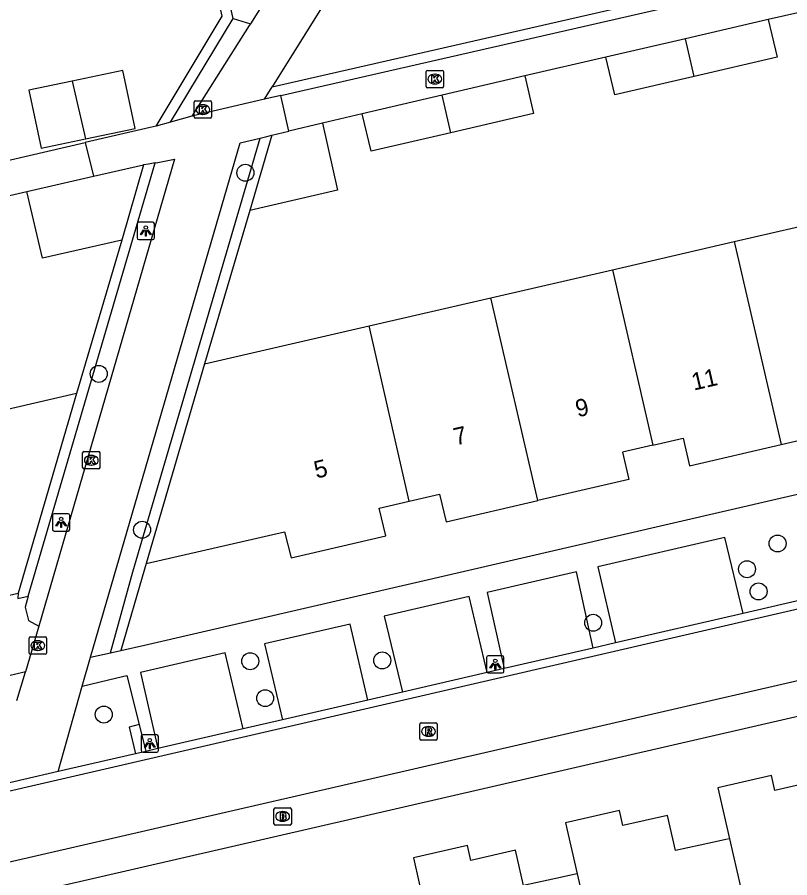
# Model space of a CAD drawing. Extents: x 156414 to 157775, y 382335 to 383765.
# Drawn here: x 156721.03 to 156765.54, y 382800.66 to 382850.26 of the extents above; entities that cross this region are included whole.
import ezdxf

# ---------------------------------------------------------------- set-up
doc = ezdxf.new("R2010")
doc.units = 0
for name, color, linetype in [('IMGEO_Berm_groen', 7, 'Continuous'), ('IMGEO_Boom', 7, 'Continuous'), ('IMGEO_Brandkraan', 7, 'Continuous'), ('IMGEO_Groenvoorziening', 7, 'Continuous'), ('IMGEO_Haag', 7, 'Continuous'), ('IMGEO_Kolk', 7, 'Continuous'), ('IMGEO_Lichtpunt', 7, 'Continuous'), ('IMGEO_Pand', 7, 'Continuous'), ('IMGEO_Pand_nummerreeks', 7, 'Continuous'), ('IMGEO_Rijbaan_lokaal_gesloten', 7, 'Continuous'), ('IMGEO_Rijbaan_lokaal_open', 7, 'Continuous'), ('IMGEO_Rioolput', 7, 'Continuous'), ('IMGEO_Voetpad_open', 7, 'Continuous')]:
    doc.layers.add(name, color=color, linetype=linetype)

msp = doc.modelspace()

# ---------------------------------------------------------------- linework, layer by layer
at = {"layer": 'IMGEO_Berm_groen'}
msp.add_lwpolyline([(156721.664, 382816.893), (156721.493, 382816.251), (156721.685, 382815.494), (156722.274, 382815.156)], dxfattribs=at)
at = {"layer": 'IMGEO_Boom'}
for centre in [(156734.173, 382841.29), (156725.727, 382829.702), (156728.226, 382820.715), (156764.843, 382819.925), (156763.079, 382818.443), (156763.742, 382817.164), (156754.215, 382815.36), (156734.456, 382813.141), (156742.063, 382813.189), (156735.315, 382811.011), (156726.015, 382810.066)]:
    msp.add_circle(centre, 0.489, dxfattribs=at)
at = {"layer": 'IMGEO_Brandkraan'}
for p, q in [((156735.897, 382804.694), (156736.749, 382804.694)), ((156735.822, 382803.768), (156735.822, 382804.62)), ((156736.31, 382804.474), (156736.335, 382804.474)), ((156736.823, 382804.62), (156736.823, 382803.768)), ((156736.749, 382803.694), (156735.897, 382803.694)), ((156736.333, 382803.914), (156736.308, 382803.914))]:
    msp.add_line(p, q, dxfattribs=at)
for points in [[(156735.897, 382804.694), (156736.749, 382804.694)], [(156735.822, 382803.768), (156735.822, 382804.62)], [(156736.17, 382804.394), (156736.17, 382803.994), (156736.383, 382803.994)], [(156736.401, 382804.394), (156736.17, 382804.394)], [(156736.349, 382804.313), (156736.295, 382804.313), (156736.295, 382804.237)], [(156736.295, 382804.237), (156736.348, 382804.237)], [(156736.823, 382804.62), (156736.823, 382803.768)], [(156736.749, 382803.694), (156735.897, 382803.694)], [(156736.357, 382804.161), (156736.295, 382804.161), (156736.295, 382804.08)], [(156736.295, 382804.08), (156736.357, 382804.08)]]:
    msp.add_lwpolyline(points, dxfattribs=at)
for centre, radius, start, end in [((156735.899, 382804.618), 0.0765, 91.552, 178.448), ((156735.899, 382804.618), 0.0765, 91.552, 178.448), ((156736.747, 382804.618), 0.0765, 1.552, 88.448), ((156736.747, 382804.618), 0.0765, 1.552, 88.448), ((156736.35, 382804.275), 0.0379, 267.8285, 90.9355), ((156736.405, 382804.249), 0.145, 59.4692, 91.5367), ((156736.43, 382804.296), 0.0922, 285.5137, 58.1501), ((156736.435, 382804.104), 0.105, 301.3115, 78.989), ((156735.899, 382803.77), 0.0765, 181.552, 268.448), ((156735.899, 382803.77), 0.0765, 181.552, 268.448), ((156736.358, 382804.12), 0.0404, 269.8759, 90.5077), ((156736.389, 382804.245), 0.251, 268.6676, 293.5347), ((156736.747, 382803.77), 0.0765, 271.552, 358.448), ((156736.747, 382803.77), 0.0765, 271.552, 358.448)]:
    msp.add_arc(centre, radius, start, end, dxfattribs=at)
for centre, major_axis, ratio, start_param, end_param in [((156736.309, 382804.194), (-0.387, 0.002), 0.722429, 4.712389, 7.853982), ((156736.334, 382804.194), (-0.39, 0.002), 0.717154, 1.570796, 4.712389)]:
    msp.add_ellipse(centre, major_axis=major_axis, ratio=ratio, start_param=start_param, end_param=end_param, dxfattribs=at)
at = {"layer": 'IMGEO_Groenvoorziening'}
msp.add_lwpolyline([(156733.462, 382850.192), (156734.46, 382849.883)], dxfattribs=at)
at = {"layer": 'IMGEO_Haag'}
for points in [[(156733.462, 382850.192), (156729.614, 382867.185), (156746.459, 382871.069), (156750.554, 382877.778)], [(156729.028, 382843.982), (156732.84, 382850.322), (156731.46, 382856.456)], [(156735.72, 382846.251), (156762.237, 382852.326)], [(156729.869, 382844.215), (156733.462, 382850.192)], [(156726.403, 382813.631), (156727.692, 382818.286), (156735.021, 382843.289)], [(156721.664, 382816.893), (156728.973, 382841.864)], [(156734.427, 382839.126), (156731.822, 382830.272)], [(156727.052, 382837.412), (156724.448, 382828.561)], [(156728.459, 382818.77), (156728.362, 382818.44), (156726.991, 382813.763)], [(156721.09, 382817.069), (156721.055, 382816.753), (156721.664, 382816.893)], [(156728.053, 382809.486), (156727.47, 382809.343), (156727.852, 382807.81)]]:
    msp.add_lwpolyline(points, dxfattribs=at)
at = {"layer": 'IMGEO_Kolk'}
for p, q in [((156744.589, 382846.268), (156744.589, 382847.12)), ((156744.664, 382847.194), (156745.516, 382847.194)), ((156745.077, 382846.974), (156745.102, 382846.974)), ((156745.59, 382847.12), (156745.59, 382846.268)), ((156745.1, 382846.414), (156745.075, 382846.414)), ((156745.516, 382846.194), (156744.664, 382846.194)), ((156731.218, 382844.509), (156731.218, 382845.361)), ((156731.293, 382845.435), (156732.145, 382845.435)), ((156732.219, 382845.361), (156732.219, 382844.509)), ((156731.706, 382845.215), (156731.731, 382845.215)), ((156732.145, 382844.435), (156731.293, 382844.435)), ((156731.729, 382844.655), (156731.704, 382844.655)), ((156724.796, 382824.299), (156724.796, 382825.151)), ((156724.871, 382825.225), (156725.723, 382825.225)), ((156725.284, 382825.005), (156725.309, 382825.005)), ((156725.797, 382825.151), (156725.797, 382824.299)), ((156725.723, 382824.225), (156724.871, 382824.225)), ((156725.307, 382824.445), (156725.282, 382824.445)), ((156721.709, 382813.613), (156721.709, 382814.465)), ((156721.784, 382814.539), (156722.636, 382814.539)), ((156722.197, 382814.319), (156722.222, 382814.319)), ((156722.71, 382814.465), (156722.71, 382813.613)), ((156722.22, 382813.759), (156722.195, 382813.759)), ((156722.636, 382813.539), (156721.784, 382813.539))]:
    msp.add_line(p, q, dxfattribs=at)
for points in [[(156744.589, 382846.268), (156744.589, 382847.12)], [(156744.664, 382847.194), (156745.516, 382847.194)], [(156744.91, 382846.894), (156745.033, 382846.894), (156745.033, 382846.743), (156745.163, 382846.894), (156745.327, 382846.894), (156745.181, 382846.743), (156745.334, 382846.494), (156745.182, 382846.494), (156745.097, 382846.658), (156745.033, 382846.591), (156745.033, 382846.494), (156744.91, 382846.494), (156744.91, 382846.894)], [(156745.59, 382847.12), (156745.59, 382846.268)], [(156745.516, 382846.194), (156744.664, 382846.194)], [(156731.218, 382844.509), (156731.218, 382845.361)], [(156731.293, 382845.435), (156732.145, 382845.435)], [(156732.219, 382845.361), (156732.219, 382844.509)], [(156731.539, 382845.135), (156731.662, 382845.135), (156731.662, 382844.984), (156731.792, 382845.135), (156731.956, 382845.135), (156731.81, 382844.984), (156731.963, 382844.735), (156731.811, 382844.735), (156731.726, 382844.899), (156731.662, 382844.832), (156731.662, 382844.735), (156731.539, 382844.735), (156731.539, 382845.135)], [(156732.145, 382844.435), (156731.293, 382844.435)], [(156724.796, 382824.299), (156724.796, 382825.151)], [(156724.871, 382825.225), (156725.723, 382825.225)], [(156725.797, 382825.151), (156725.797, 382824.299)], [(156725.117, 382824.925), (156725.24, 382824.925), (156725.24, 382824.774), (156725.37, 382824.925), (156725.534, 382824.925), (156725.388, 382824.774), (156725.541, 382824.525), (156725.389, 382824.525), (156725.304, 382824.689), (156725.24, 382824.622), (156725.24, 382824.525), (156725.117, 382824.525), (156725.117, 382824.925)], [(156725.723, 382824.225), (156724.871, 382824.225)], [(156721.709, 382813.613), (156721.709, 382814.465)], [(156721.784, 382814.539), (156722.636, 382814.539)], [(156722.03, 382814.239), (156722.153, 382814.239), (156722.153, 382814.088), (156722.283, 382814.239), (156722.447, 382814.239), (156722.301, 382814.088), (156722.454, 382813.839), (156722.302, 382813.839), (156722.217, 382814.003), (156722.153, 382813.936), (156722.153, 382813.839), (156722.03, 382813.839), (156722.03, 382814.239)], [(156722.71, 382814.465), (156722.71, 382813.613)], [(156722.636, 382813.539), (156721.784, 382813.539)]]:
    msp.add_lwpolyline(points, dxfattribs=at)
for centre, start, end in [((156744.666, 382847.118), 91.552, 178.448), ((156744.666, 382847.118), 91.552, 178.448), ((156745.514, 382847.118), 1.552, 88.448), ((156745.514, 382847.118), 1.552, 88.448), ((156744.666, 382846.27), 181.552, 268.448), ((156744.666, 382846.27), 181.552, 268.448), ((156745.514, 382846.27), 271.552, 358.448), ((156745.514, 382846.27), 271.552, 358.448), ((156731.295, 382845.359), 91.552, 178.448), ((156731.295, 382845.359), 91.552, 178.448), ((156732.143, 382845.359), 1.552, 88.448), ((156732.143, 382845.359), 1.552, 88.448), ((156731.295, 382844.511), 181.552, 268.448), ((156731.295, 382844.511), 181.552, 268.448), ((156732.143, 382844.511), 271.552, 358.448), ((156732.143, 382844.511), 271.552, 358.448), ((156724.873, 382825.149), 91.552, 178.448), ((156724.873, 382825.149), 91.552, 178.448), ((156725.721, 382825.149), 1.552, 88.448), ((156725.721, 382825.149), 1.552, 88.448), ((156724.873, 382824.301), 181.552, 268.448), ((156724.873, 382824.301), 181.552, 268.448), ((156725.721, 382824.301), 271.552, 358.448), ((156725.721, 382824.301), 271.552, 358.448), ((156721.786, 382814.463), 91.552, 178.448), ((156721.786, 382814.463), 91.552, 178.448), ((156722.634, 382814.463), 1.552, 88.448), ((156722.634, 382814.463), 1.552, 88.448), ((156721.786, 382813.615), 181.552, 268.448), ((156721.786, 382813.615), 181.552, 268.448), ((156722.634, 382813.615), 271.552, 358.448), ((156722.634, 382813.615), 271.552, 358.448)]:
    msp.add_arc(centre, 0.0765, start, end, dxfattribs=at)
for centre, major_axis, ratio, start_param, end_param in [((156745.076, 382846.694), (-0.387, 0.002), 0.722429, 4.712389, 7.853982), ((156745.101, 382846.694), (-0.39, 0.002), 0.717154, 1.570796, 4.712389), ((156731.705, 382844.935), (-0.387, 0.002), 0.722429, 4.712389, 7.853982), ((156731.73, 382844.935), (-0.39, 0.002), 0.717154, 1.570796, 4.712389), ((156725.283, 382824.725), (-0.387, 0.002), 0.722429, 4.712389, 7.853982), ((156725.308, 382824.725), (-0.39, 0.002), 0.717154, 1.570796, 4.712389), ((156722.196, 382814.039), (-0.387, 0.002), 0.722429, 4.712389, 7.853982), ((156722.221, 382814.039), (-0.39, 0.002), 0.717154, 1.570796, 4.712389)]:
    msp.add_ellipse(centre, major_axis=major_axis, ratio=ratio, start_param=start_param, end_param=end_param, dxfattribs=at)
at = {"layer": 'IMGEO_Lichtpunt'}
for p, q in [((156728.84, 382838.437), (156728.032, 382838.437)), ((156728.84, 382838.437), (156728.032, 382838.437)), ((156727.938, 382838.342), (156727.938, 382837.535)), ((156727.938, 382838.342), (156727.938, 382837.535)), ((156728.934, 382837.535), (156728.934, 382838.342)), ((156728.934, 382837.535), (156728.934, 382838.342)), ((156728.032, 382837.441), (156728.84, 382837.441)), ((156728.032, 382837.441), (156728.84, 382837.441)), ((156723.059, 382821.545), (156723.059, 382820.738)), ((156723.059, 382821.545), (156723.059, 382820.738)), ((156723.961, 382821.64), (156723.153, 382821.64)), ((156723.961, 382821.64), (156723.153, 382821.64)), ((156724.055, 382820.738), (156724.055, 382821.545)), ((156724.055, 382820.738), (156724.055, 382821.545)), ((156723.153, 382820.644), (156723.961, 382820.644)), ((156723.153, 382820.644), (156723.961, 382820.644)), ((156748.077, 382813.363), (156748.077, 382812.556)), ((156748.077, 382813.363), (156748.077, 382812.556)), ((156748.979, 382813.458), (156748.171, 382813.458)), ((156748.979, 382813.458), (156748.171, 382813.458)), ((156749.073, 382812.556), (156749.073, 382813.363)), ((156749.073, 382812.556), (156749.073, 382813.363)), ((156748.171, 382812.462), (156748.979, 382812.462)), ((156748.171, 382812.462), (156748.979, 382812.462)), ((156728.166, 382808.793), (156728.166, 382807.986)), ((156728.166, 382808.793), (156728.166, 382807.986)), ((156729.068, 382808.888), (156728.26, 382808.888)), ((156729.068, 382808.888), (156728.26, 382808.888)), ((156729.162, 382807.986), (156729.162, 382808.793)), ((156729.162, 382807.986), (156729.162, 382808.793)), ((156728.26, 382807.892), (156729.068, 382807.892)), ((156728.26, 382807.892), (156729.068, 382807.892))]:
    msp.add_line(p, q, dxfattribs=at)
for points in [[(156728.312, 382838.006), (156728.351, 382837.978), (156728.163, 382837.716), (156728.125, 382837.743), (156728.312, 382838.006)], [(156728.414, 382837.958), (156728.461, 382837.958), (156728.461, 382837.636), (156728.414, 382837.636), (156728.414, 382837.958)], [(156728.524, 382837.978), (156728.562, 382838.005), (156728.749, 382837.743), (156728.71, 382837.715), (156728.524, 382837.978)], [(156723.433, 382821.209), (156723.472, 382821.181), (156723.284, 382820.919), (156723.246, 382820.946), (156723.433, 382821.209)], [(156723.535, 382821.161), (156723.582, 382821.161), (156723.582, 382820.839), (156723.535, 382820.839), (156723.535, 382821.161)], [(156723.645, 382821.181), (156723.683, 382821.208), (156723.87, 382820.946), (156723.831, 382820.918), (156723.645, 382821.181)], [(156748.451, 382813.027), (156748.49, 382812.999), (156748.302, 382812.737), (156748.264, 382812.764), (156748.451, 382813.027)], [(156748.553, 382812.979), (156748.6, 382812.979), (156748.6, 382812.657), (156748.553, 382812.657), (156748.553, 382812.979)], [(156748.663, 382812.999), (156748.701, 382813.026), (156748.888, 382812.764), (156748.849, 382812.736), (156748.663, 382812.999)], [(156728.54, 382808.457), (156728.579, 382808.429), (156728.391, 382808.167), (156728.353, 382808.194), (156728.54, 382808.457)], [(156728.642, 382808.409), (156728.689, 382808.409), (156728.689, 382808.087), (156728.642, 382808.087), (156728.642, 382808.409)], [(156728.752, 382808.429), (156728.79, 382808.456), (156728.977, 382808.194), (156728.938, 382808.166), (156728.752, 382808.429)]]:
    msp.add_lwpolyline(points, dxfattribs=at)
for centre in [(156728.437, 382838.14), (156723.558, 382821.343), (156748.576, 382813.161), (156728.665, 382808.591)]:
    msp.add_circle(centre, 0.0994, dxfattribs=at)
for centre, start, end in [((156728.032, 382838.342), 90, 180), ((156728.032, 382838.342), 90, 180), ((156728.84, 382838.342), 0, 90), ((156728.84, 382838.342), 0, 90), ((156728.032, 382837.535), 180, 270), ((156728.032, 382837.535), 180, 270), ((156728.84, 382837.535), 270, 0), ((156728.84, 382837.535), 270, 360), ((156723.153, 382821.545), 90, 180), ((156723.153, 382821.545), 90, 180), ((156723.961, 382821.545), 0, 90), ((156723.961, 382821.545), 0, 90), ((156723.153, 382820.738), 180, 270), ((156723.153, 382820.738), 180, 270), ((156723.961, 382820.738), 270, 0), ((156723.961, 382820.738), 270, 360), ((156748.171, 382813.363), 90, 180), ((156748.171, 382813.363), 90, 180), ((156748.979, 382813.363), 0, 90), ((156748.979, 382813.363), 0, 90), ((156748.171, 382812.556), 180, 270), ((156748.171, 382812.556), 180, 270), ((156748.979, 382812.556), 270, 0), ((156748.979, 382812.556), 270, 360), ((156728.26, 382808.793), 90, 180), ((156728.26, 382808.793), 90, 180), ((156729.068, 382808.793), 0, 90), ((156729.068, 382808.793), 0, 90), ((156728.26, 382807.986), 180, 270), ((156728.26, 382807.986), 180, 270), ((156729.068, 382807.986), 270, 0), ((156729.068, 382807.986), 270, 360)]:
    msp.add_arc(centre, 0.0946, start, end, dxfattribs=at)
at = {"layer": 'IMGEO_Pand'}
for points in [[(156764.29, 382850.124), (156759.529, 382849.02)], [(156764.29, 382850.124), (156764.82, 382847.954), (156760.03, 382846.849)], [(156759.529, 382849.02), (156754.942, 382847.957)], [(156760.03, 382846.849), (156759.529, 382849.02)], [(156760.03, 382846.849), (156755.457, 382845.794), (156754.942, 382847.957)], [(156724.967, 382843.252), (156727.822, 382843.851), (156727.121, 382847.192), (156724.198, 382846.579)], [(156750.279, 382846.872), (156745.506, 382845.761)], [(156750.279, 382846.872), (156750.781, 382844.707), (156746.004, 382843.602)], [(156724.198, 382846.579), (156721.7, 382846.054), (156722.401, 382842.714), (156724.967, 382843.252)], [(156724.198, 382846.579), (156724.967, 382843.252)], [(156745.506, 382845.761), (156740.913, 382844.692)], [(156746.004, 382843.602), (156745.506, 382845.761)], [(156746.004, 382843.602), (156741.43, 382842.544), (156740.913, 382844.692)], [(156738.623, 382844.151), (156739.488, 382840.289), (156734.427, 382839.126)], [(156738.623, 382844.151), (156736.682, 382843.688)], [(156735.694, 382843.452), (156734.427, 382839.126)], [(156735.694, 382843.452), (156736.682, 382843.688)], [(156725.424, 382841.088), (156728.312, 382841.742)], [(156728.312, 382841.742), (156727.052, 382837.412)], [(156721.59, 382840.219), (156725.424, 382841.088)], [(156727.052, 382837.412), (156722.476, 382836.371), (156721.59, 382840.219)], [(156762.345, 382837.325), (156769.36, 382838.946)], [(156755.331, 382835.704), (156762.345, 382837.325)], [(156762.345, 382837.325), (156765.048, 382825.633)], [(156748.317, 382834.083), (156755.331, 382835.704)], [(156755.331, 382835.704), (156757.658, 382825.595)], [(156741.303, 382832.463), (156748.317, 382834.083)], [(156751.018, 382822.4), (156748.317, 382834.083)], [(156731.822, 382830.272), (156741.303, 382832.463)], [(156743.617, 382822.365), (156741.303, 382832.463)], [(156731.822, 382830.272), (156728.459, 382818.77)], [(156724.448, 382828.561), (156708.947, 382824.977)], [(156724.448, 382828.561), (156721.09, 382817.069)], [(156765.048, 382825.633), (156770.313, 382826.852), (156769.935, 382828.448), (156771.693, 382828.853)], [(156757.658, 382825.595), (156759.399, 382825.998), (156759.766, 382824.41), (156765.048, 382825.633)], [(156757.658, 382825.595), (156755.911, 382825.191), (156756.278, 382823.614), (156751.018, 382822.4)], [(156743.617, 382822.365), (156745.369, 382822.769), (156745.735, 382821.181), (156751.018, 382822.4)], [(156728.459, 382818.77), (156736.42, 382820.595), (156736.812, 382819.1), (156742.266, 382820.374), (156741.88, 382821.964), (156743.617, 382822.365)], [(156711.29, 382814.805), (156713.021, 382815.212), (156713.378, 382813.694), (156718.826, 382814.976), (156718.487, 382816.475), (156721.09, 382817.069)], [(156770.837, 382804.948), (156770.627, 382804.901), (156770.011, 382804.764), (156767.728, 382804.254), (156767.262, 382806.281), (156764.689, 382805.69), (156764.492, 382806.547), (156761.396, 382805.835), (156762.07, 382802.905)], [(156762.07, 382802.905), (156761.86, 382802.859), (156761.094, 382802.691), (156758.959, 382802.223), (156758.5, 382804.252), (156755.925, 382803.67), (156755.731, 382804.528), (156752.619, 382803.824), (156753.294, 382800.894)], [(156762.07, 382802.905), (156764.402, 382792.758)], [(156753.294, 382800.894), (156753.109, 382800.853), (156752.332, 382800.682), (156750.209, 382800.213), (156749.747, 382802.241), (156747.173, 382801.655), (156746.977, 382802.513), (156743.854, 382801.802), (156744.524, 382798.891)], [(156753.294, 382800.894), (156755.634, 382790.738)]]:
    msp.add_lwpolyline(points, dxfattribs=at)
at = {"layer": 'IMGEO_Rijbaan_lokaal_gesloten'}
for points in [[(156704.67, 382802.003), (156706.623, 382802.451), (156776.982, 382818.697), (156816.178, 382827.739), (156855.39, 382836.785), (156925.817, 382853.068)], [(156926.664, 382849.268), (156923.197, 382848.454), (156856.378, 382832.904), (156817.084, 382823.811), (156780.281, 382815.295), (156707.464, 382798.538)]]:
    msp.add_lwpolyline(points, dxfattribs=at)
at = {"layer": 'IMGEO_Rijbaan_lokaal_open'}
for points in [[(156766.74, 382816.788), (156762.858, 382815.891)], [(156762.858, 382815.891), (156755.496, 382814.192)], [(156755.496, 382814.192), (156754.223, 382813.898)], [(156754.223, 382813.898), (156749.094, 382812.714)], [(156749.094, 382812.714), (156748.109, 382812.486)], [(156748.109, 382812.486), (156743.228, 382811.36)], [(156743.228, 382811.36), (156741.228, 382810.898)], [(156741.228, 382810.898), (156736.304, 382809.761)], [(156736.304, 382809.761), (156734.056, 382809.242)], [(156734.056, 382809.242), (156729.128, 382808.105)], [(156727.852, 382807.81), (156723.383, 382806.779)], [(156728.437, 382807.945), (156727.852, 382807.81)], [(156729.128, 382808.105), (156728.437, 382807.945)], [(156723.383, 382806.779), (156719.402, 382805.859)]]:
    msp.add_lwpolyline(points, dxfattribs=at)
at = {"layer": 'IMGEO_Rioolput'}
for p, q in [((156744.221, 382808.666), (156744.221, 382809.518)), ((156744.296, 382809.592), (156745.148, 382809.592)), ((156744.709, 382809.372), (156744.734, 382809.372)), ((156745.222, 382809.518), (156745.222, 382808.666)), ((156744.732, 382808.812), (156744.707, 382808.812)), ((156745.148, 382808.592), (156744.296, 382808.592))]:
    msp.add_line(p, q, dxfattribs=at)
for points in [[(156744.221, 382808.666), (156744.221, 382809.518)], [(156744.296, 382809.592), (156745.148, 382809.592)], [(156744.81, 382809.29), (156744.558, 382809.292), (156744.558, 382808.892)], [(156744.736, 382809.211), (156744.682, 382809.211), (156744.682, 382809.13)], [(156744.682, 382809.13), (156744.734, 382809.13)], [(156745.222, 382809.518), (156745.222, 382808.666)], [(156744.558, 382808.892), (156744.682, 382808.892), (156744.682, 382809.054), (156744.693, 382809.054)], [(156744.74, 382809.025), (156744.811, 382808.892), (156744.951, 382808.892), (156744.886, 382809.018)], [(156745.148, 382808.592), (156744.296, 382808.592)]]:
    msp.add_lwpolyline(points, dxfattribs=at)
for centre, radius, start, end in [((156744.298, 382809.516), 0.0765, 91.552, 178.448), ((156744.298, 382809.516), 0.0765, 91.552, 178.448), ((156744.718, 382809.319), 0.19, 274.7715, 282.9687), ((156744.742, 382809.115), 0.0964, 77.0061, 93.1865), ((156744.756, 382809.172), 0.0378, 276.6634, 79.6772), ((156744.809, 382809.18), 0.109, 350.3612, 89.416), ((156744.807, 382809.18), 0.112, 277.5842, 350.9817), ((156745.146, 382809.516), 0.0765, 1.552, 88.448), ((156745.146, 382809.516), 0.0765, 1.552, 88.448), ((156744.298, 382808.668), 0.0765, 181.552, 268.448), ((156744.298, 382808.668), 0.0765, 181.552, 268.448), ((156744.692, 382809.001), 0.0533, 26.0293, 88.6989), ((156744.791, 382808.965), 0.108, 29.5134, 73.7905), ((156745.146, 382808.668), 0.0765, 271.552, 358.448), ((156745.146, 382808.668), 0.0765, 271.552, 358.448)]:
    msp.add_arc(centre, radius, start, end, dxfattribs=at)
for centre, major_axis, ratio, start_param, end_param in [((156744.708, 382809.092), (-0.387, 0.002), 0.722429, 4.712389, 7.853982), ((156744.733, 382809.092), (-0.39, 0.002), 0.717154, 1.570796, 4.712389)]:
    msp.add_ellipse(centre, major_axis=major_axis, ratio=ratio, start_param=start_param, end_param=end_param, dxfattribs=at)
at = {"layer": 'IMGEO_Voetpad_open'}
for points in [[(156756.129, 382878.945), (156735.72, 382846.251)], [(156752.234, 382878.165), (156734.46, 382849.883)], [(156736.219, 382845.75), (156762.371, 382851.741)], [(156768.997, 382851.179), (156764.29, 382850.124)], [(156734.46, 382849.883), (156734.391, 382849.773), (156731.086, 382844.552)], [(156754.942, 382847.957), (156750.279, 382846.872)], [(156735.272, 382845.533), (156735.72, 382846.251)], [(156735.272, 382845.533), (156731.086, 382844.552)], [(156736.219, 382845.75), (156735.272, 382845.533)], [(156736.682, 382843.688), (156736.219, 382845.75)], [(156731.086, 382844.552), (156729.869, 382844.215)], [(156740.913, 382844.692), (156738.623, 382844.151)], [(156729.028, 382843.982), (156728.68, 382843.901), (156724.949, 382843.035)], [(156729.869, 382844.215), (156729.028, 382843.982)], [(156735.021, 382843.289), (156735.414, 382843.384), (156735.694, 382843.452)], [(156710.108, 382839.592), (156724.949, 382843.035)], [(156724.949, 382843.035), (156725.424, 382841.088)], [(156725.241, 382813.37), (156733.866, 382843.011), (156735.021, 382843.289)], [(156728.973, 382841.864), (156729.13, 382841.893), (156730.097, 382842.072), (156722.274, 382815.156)], [(156726.991, 382813.763), (156728.366, 382814.072), (156850.038, 382842.208)], [(156728.973, 382841.864), (156728.587, 382841.793), (156728.312, 382841.742)], [(156706.264, 382836.69), (156721.59, 382840.219)], [(156762.858, 382815.891), (156761.803, 382820.273), (156754.476, 382818.58), (156755.496, 382814.192)], [(156754.223, 382813.898), (156753.263, 382818.3), (156748.111, 382817.109), (156749.094, 382812.714)], [(156748.109, 382812.486), (156747.06, 382816.866), (156742.169, 382815.736), (156743.228, 382811.36)], [(156722.274, 382815.156), (156721.508, 382812.519)], [(156741.228, 382810.898), (156740.217, 382815.285), (156735.282, 382814.144), (156736.304, 382809.761)], [(156725.241, 382813.37), (156726.403, 382813.631)], [(156726.403, 382813.631), (156726.991, 382813.763)], [(156734.056, 382809.242), (156733.008, 382813.619), (156728.137, 382812.493), (156729.128, 382808.105)], [(156724.76, 382811.71), (156725.241, 382813.37)], [(156707.908, 382796.596), (156778.432, 382812.831)], [(156721.508, 382812.519), (156720.868, 382812.371), (156719.687, 382812.099), (156705.153, 382808.749)], [(156720.999, 382810.871), (156721.508, 382812.519)], [(156724.76, 382811.71), (156726.763, 382812.175), (156727.348, 382812.311), (156728.053, 382809.486)], [(156723.383, 382806.779), (156724.76, 382811.71)], [(156728.053, 382809.486), (156728.437, 382807.945)]]:
    msp.add_lwpolyline(points, dxfattribs=at)

# ---------------------------------------------------------------- texts
at = {"layer": 'IMGEO_Pand_nummerreeks'}
for s, rotation, p in [('11', 13.0041, (156760.007, 382828.736)), ('9', 13.0041, (156753.319, 382827.192)), ('7', 13.0041, (156746.294, 382825.57)), ('5', 14.0757, (156738.27, 382823.657))]:
    msp.add_text(s, height=1, rotation=rotation, dxfattribs=at).set_placement(p)

doc.saveas('drawing.dxf')
